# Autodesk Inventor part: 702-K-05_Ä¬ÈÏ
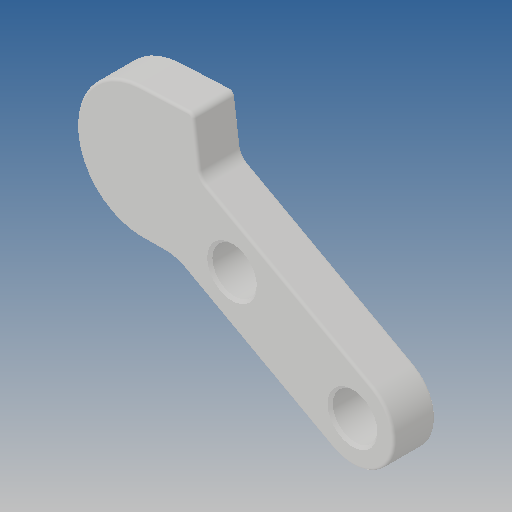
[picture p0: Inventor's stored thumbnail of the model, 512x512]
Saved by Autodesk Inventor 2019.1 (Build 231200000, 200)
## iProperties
Created: 2010-06
Part Number: 702-K-05_Ä¬ÈÏ
Material: Ogólny
Document SubType Name: Modeling
Designer: CADENGINEERING4
Density: 1 g/cm^3
Appearance: Domyślna
Author: CADENGINEERING4
Revision Number: ÈÎºÎ
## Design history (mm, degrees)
feature "NONE"
node "Bryła1"
